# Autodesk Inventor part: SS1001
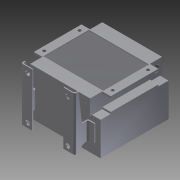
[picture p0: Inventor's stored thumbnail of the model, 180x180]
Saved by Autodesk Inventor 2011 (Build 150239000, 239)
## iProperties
Created: 2011-08
Part Number: SS1001
Document SubType Name: Modeling
Designer: khramov
Density: 1 g/cm^3
Author: khramov
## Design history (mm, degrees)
sketch "Эскиз1"
  geometry: L1 (0, 0)-(226, 0); L2 (226, 0)-(226, -200); L3 (226, -200)-(0, -200); L4 (0, -200)-(0, 0)
  constraints: 8 end point, 2 parallel, 1 horizontal, 1 perpendicular
  dimensions: "d0" = 226 distance of L1.start L1.end; "d1" = 200 distance of L3.end L1.start
extrude "Выдавливание1" new body sketch "Эскиз1" distance "d2" = 98; taper "d3" = 0 deg
sketch "Эскиз2"
  geometry: L1 (0, 0)-(-226, 0) reference; L2 (-226, 0)-(-226, -200) reference; L3 (-226, -200)-(0, -200) reference; L4 (0, -200)-(0, 0) reference; L5 (-226, -100)-(0, -100); L6 (-113, 0)-(-113, -200); C1 r 83.5 at (-113, -100)
  constraints: 5 midpoint, 4 end point, 1 centre point
  dimensions: "d4" = 167 diameter of C1
extrude "Выдавливание2" join sketch "Эскиз2" distance "d5" = 15; taper "d6" = 0 deg
sketch "Эскиз3"
  geometry: L1 (226, -200)-(0, -200) reference; L2 (0, -206)-(226, -206); L3 (226, -206)-(226, 6); L4 (226, 6)-(0, 6); L5 (0, 6)-(0, -206)
  constraints: 8 end point, 2 parallel, 1 horizontal, 1 perpendicular
  dimensions: "d7" = 212 distance of L4.end L2.start; "d8" = 6 distance between parallel lines of L2 L1
extrude "Выдавливание3" join sketch "Эскиз3" distance "d9" = 45; taper "d10" = 0 deg
sketch "Эскиз4"
  geometry: L1 (0, -45)-(226, -45) reference; L2 (0, 0)-(0, -45) reference; L3 (0, -40)-(25, -40); L4 (25, -40)-(25, -5); L5 (25, -5)-(0, -5); L6 (0, -5)-(0, -40); L7 (113, -45)-(113, 159.322); L8 (201, -40)-(201, -5); L9 (226, -40)-(201, -40); L10 (201, -5)-(226, -5); L11 (226, -5)-(226, -40); 1 further point
  constraints: 18 end point, 4 symmetric about line, 3 parallel, 1 horizontal, 1 midpoint, 1 perpendicular, 1 point on line
  dimensions: "d11" = 35 distance of L3.end L4.end; "d12" = 5 distance between parallel lines of L3 L1; "d13" = 25 distance of L3.start L3.end
extrude "Выдавливание4" cut sketch "Эскиз4" stored distance "d14" = 45; taper "d15" = 0 deg
sketch "Эскиз5"
  geometry: L1 (0, 6)-(25, 6); L2 (25, 6)-(25, -30); L3 (25, -30)-(0, -30); L4 (0, -30)-(0, 6); L5 (0, -206)-(25, -206); L6 (25, -206)-(25, -170); L7 (25, -170)-(0, -170); L8 (0, -170)-(0, -206); L9 (0, 6)-(226, 6) reference; L10 (113, 6)-(113, -206); L11 (0, -206)-(226, -206) reference; L12 (226, 6)-(201, 6); L13 (201, 6)-(201, -30); L14 (201, -30)-(226, -30); L15 (226, -30)-(226, 6); L16 (226, -206)-(201, -206); L17 (201, -206)-(201, -170); L18 (201, -170)-(226, -170); L19 (226, -170)-(226, -206); 2 further points
  constraints: 34 end point, 7 symmetric about line, 4 parallel, 2 horizontal, 2 midpoint, 2 perpendicular
  dimensions: "d16" = 36 distance of L1.end L2.end; "d17" = 36 distance of L5.end L6.end; "d18" = 140 distance between parallel lines of L3 L7 (derived); "d19" = 25 distance of L6.end L7.end; "d20" = 25 distance of L2.end L3.end
extrude "Выдавливание6" cut sketch "Эскиз5" distance "d23" = 45; taper "d24" = 0 deg
sketch "Эскиз6"
  geometry: L1 (25, -30)-(0, -30) reference; L2 (12.5, -48)-(213.5, -48); L3 (213.5, -48)-(213.5, -152); L4 (213.5, -152)-(12.5, -152); L5 (12.5, -152)-(12.5, -48); L6 (12.5, -100)-(213.5, -100); C1 r 4.5 at (12.5, -48); C2 r 4.5 at (213.5, -48); C3 r 4.5 at (213.5, -152); C4 r 4.5 at (12.5, -152); 2 further points
  constraints: 10 end point, 4 centre point, 4 coincident, 2 midpoint, 2 parallel, 1 horizontal, 1 perpendicular
  dimensions: "d25" = 201 distance of L2.start L2.end; "d26" = 104 distance of L4.end L2.start; "d27" = 140 distance of point (0, -170) L1.end (derived); "d28" = 70 distance between parallel lines of L6 L1; "d29" = 9 diameter of C1; "d30" = 9 diameter of C2; "d31" = 9 diameter of C3; "d32" = 9 diameter of C4
extrude "Выдавливание7" cut sketch "Эскиз6" stored distance "d33" = 45; taper "d34" = 0 deg
sketch "Эскиз7"
  geometry: L1 (25, -30)-(0, -30) reference; L2 (0, -170)-(25, -170) reference; L3 (25, -30)-(25, -170) reference; L4 (201, -30)-(201, -170) reference; L5 (25, -33)-(201, -33); L6 (201, -33)-(201, -167); L7 (201, -167)-(25, -167); L8 (25, -167)-(25, -33); 1 further point
  constraints: 8 end point, 2 parallel, 2 point on line, 1 horizontal, 1 perpendicular
  dimensions: "d35" = 3 distance between parallel lines of L5 L1; "d36" = 3 distance between parallel lines of L2 L7
extrude "Выдавливание8" cut sketch "Эскиз7" distance "d37" = 2; taper "d38" = 0 deg
sketch "Эскиз8"
  geometry: L1 (226, -200)-(201, -200) reference; L2 (210.927, -200)-(210.927, -203); L3 (201, -206)-(201, -170) reference; L4 (210.927, -203)-(197, -203); L5 (192, -208)-(192, -237); L6 (187, -242)-(159, -242); L7 (159, -242)-(159, -239); L8 (159, -239)-(184, -239); L9 (189, -234)-(189, -205); L10 (201, -206)-(25, -206) reference; L11 (194, -200)-(210.927, -200); L12 (113, -100)-(113, -313.956); L13 (25, 0)-(201, 0) reference; L14 (172, -229.595)-(172, -261.848); L15 (226, -200)-(0, -200) reference; L16 (15.073, -200)-(15.073, -203); L17 (15.073, -203)-(29, -203); L18 (32, -200)-(15.073, -200); L19 (67, -239)-(42, -239); L20 (37, -234)-(37, -205); L21 (34, -208)-(34, -237); L22 (39, -242)-(67, -242); L23 (67, -242)-(67, -239); L24 (54, -229.595)-(54, -261.848); C1 r 83.5 at (113, -100) reference; A1 r 5 centre (187, -237) between (187, -242) and (192, -237); A2 r 5 centre (184, -234) between (184, -239) and (189, -234); A3 r 5 centre (197, -208) between (197, -203) and (192, -208); A4 r 5 centre (194, -205) between (194, -200) and (189, -205); A5 r 5 centre (32, -205) between (37, -205) and (32, -200); A6 r 5 centre (29, -208) between (34, -208) and (29, -203); A7 r 5 centre (42, -234) between (37, -234) and (42, -239); A8 r 5 centre (39, -237) between (34, -237) and (39, -242); 2 further points
  constraints: 38 end point, 19 symmetric about line, 16 point on circle, 8 centre point, 8 tangent, 5 parallel, 4 perpendicular, 3 equal radius, 1 collinear, 1 point on line, 4 other
  dimensions: "d39" = 3 distance of L6.end L7.end; "d40" = 3 distance between parallel lines of L5 L9; "d41" = 3 distance of L2.start L2.end; "d42" = 13 distance from line of L7 L14.start; "d43" = 17 distance from line of L9 L14.start; "d44" = 42 distance between parallel lines of L6 L15; "d45" = 5 radius of A1; "d47" = 59 distance between parallel lines of L12 L14; "d48" = 118 distance between parallel lines of L24 L14 (derived)
extrude "Выдавливание9" join sketch "Эскиз8" distance "d49" = 70; taper "d51" = 0 deg; dims "d50" = 86, "d52" = 0
sketch "Эскиз9"
  geometry: L1 (0, -27.593)-(85.973, -17.473); L2 (85.973, -17.473)-(85.973, 3); L3 (0, 3)-(0, -27.593); L4 (0, 3)-(85.973, 3); L5 (141.986, -17.473)-(156, -24.718); L6 (25, 3)-(0, 3) reference; L7 (156, -24.718)-(156, 3); L8 (156, -2)-(156, -31) reference; L9 (156, 3)-(135.419, 3); L10 (168, 3)-(70, 3) reference; L11 (141.986, -17.473)-(135.419, 3); 1 further point
  constraints: 16 end point, 1 collinear, 1 point on line
extrude "Выдавливание10" cut sketch "Эскиз9" distance "d53" = 500; taper "d54" = 0 deg
sketch "Эскиз10"
  geometry: L1 (13, -16.5)-(-105, -16.5); L2 (-105, -16.5)-(-105, -142.5); L3 (-105, -142.5)-(13, -142.5); L4 (13, -142.5)-(13, -16.5); L5 (-134, -25)-(42, -25) reference; L6 (37.5, -183)-(-129.5, -183) reference; L7 (-46, -183)-(-46, -269.723); C1 r 6.5 at (13, -16.5); C2 r 6.5 at (13, -142.5); C3 r 6.5 at (-105, -142.5); C4 r 6.5 at (-105, -16.5); 1 further point
  constraints: 10 end point, 4 centre point, 4 coincident, 2 parallel, 2 perpendicular, 1 horizontal, 1 midpoint
  dimensions: "d55" = 13 diameter of C1; "d56" = 13 diameter of C2; "d57" = 13 diameter of C3; "d58" = 13 diameter of C4; "d59" = 126 distance of L3.end L1.start; "d60" = 118 distance of L1.start L1.end; "d61" = 8.5 distance from line of C1.centre L5; "d63" = 59 distance between parallel lines of L2 L7
extrude "Выдавливание11" cut sketch "Эскиз10" distance "d64" = 10; taper "d65" = 0 deg
sketch "Эскиз11"
  geometry: L1 (0, 0)-(45, 0) reference; L2 (22.5, 0)-(22.5, -18); L3 (40, -36)-(45, -36) reference; 2 further points
  constraints: 2 end point, 1 coincident, 1 midpoint, 1 perpendicular
  dimensions: "d66" = 18 distance from line of point (22.5, -18) L1
hole "Отверстие1" sketch "Эскиз11" at (22.5, -18) diameter "d67" = 18.631; stored, may be unused: countersink angle "d71" = 90 deg, drill point angle "d73" = 118 deg; dims "d68" = 25, "d69" = 21, "d70" = 2, "d72" = 30
sketch "Эскиз12"
  geometry: L1 (45, -176)-(40, -176) reference; L2 (0, -206)-(45, -206); L3 (45, -206)-(45, -212); L4 (45, -212)-(0, -212); L5 (0, -212)-(0, -206); 1 further point
  constraints: 8 end point, 2 parallel, 1 horizontal, 1 perpendicular
  dimensions: "d74" = 36 distance between parallel lines of L1 L4
extrude "Выдавливание13" join sketch "Эскиз12" distance "d77" = 176; taper "d78" = 0 deg
sketch "Эскиз13"
  geometry: L1 (0, -212)-(45, -212) reference; L2 (22.5, -212)-(22.5, -194); 2 further points
  constraints: 2 end point, 1 coincident, 1 midpoint, 1 perpendicular
  dimensions: "d79" = 18 distance of L2.start L2.end
hole "Отверстие2" sketch "Эскиз13" at (22.5, -194) diameter "d80" = 18.631; stored, may be unused: countersink angle "d84" = 90 deg, drill point angle "d86" = 118 deg; dims "d81" = 25, "d82" = 21, "d83" = 2, "d85" = 30
node "Твердое тело1"
